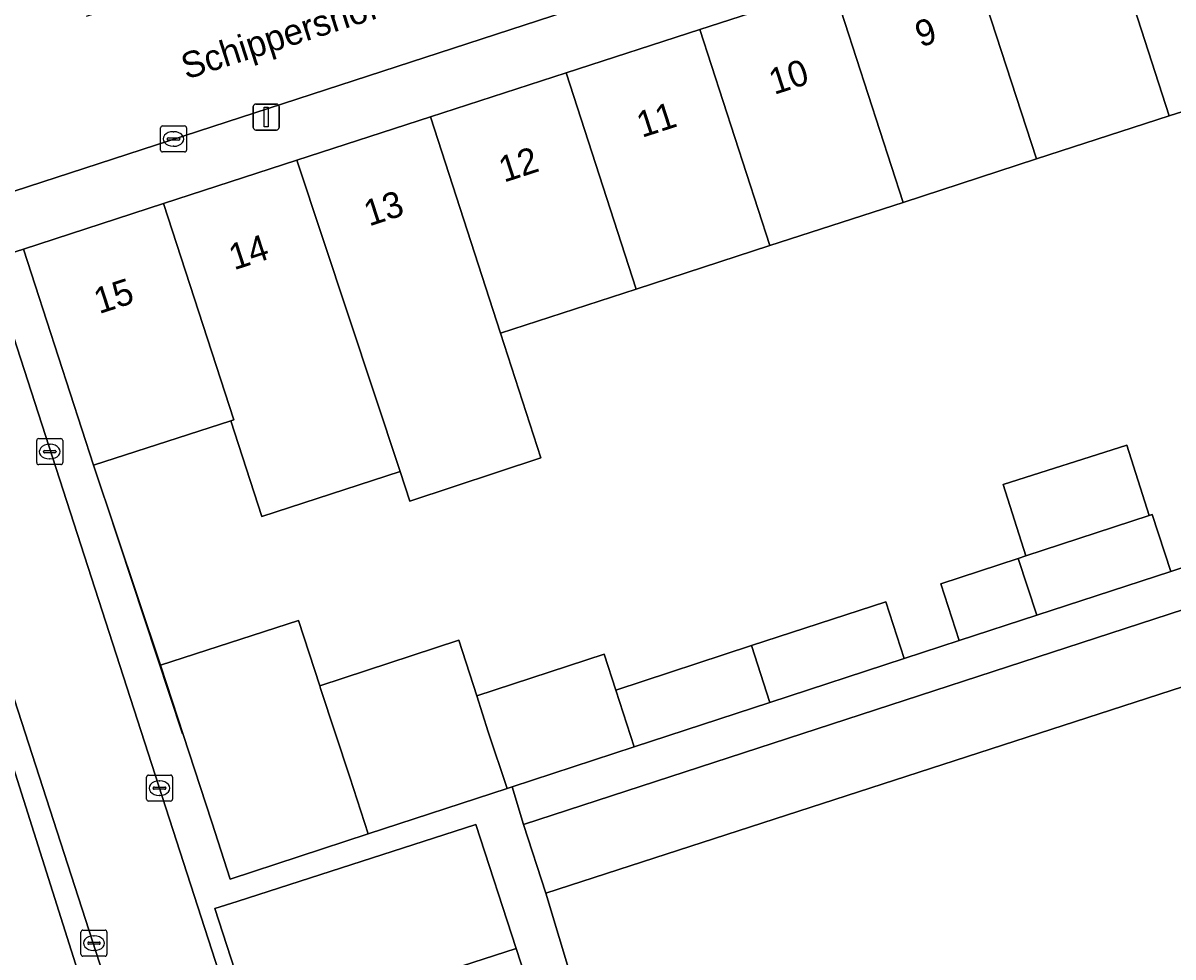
# Model space of a CAD drawing. Extents: x 159371 to 159986, y 382987 to 383597.
# Drawn here: x 159528.13 to 159572.4, y 383065.02 to 383100.96 of the extents above; entities that cross this region are included whole.
import ezdxf

# ---------------------------------------------------------------- set-up
doc = ezdxf.new("R2010")
doc.units = 0
for name, color, linetype in [('IMGEO_Erf', 7, 'Continuous'), ('IMGEO_Kolk', 7, 'Continuous'), ('IMGEO_Lichtmast', 7, 'Continuous'), ('IMGEO_Muur', 7, 'Continuous'), ('IMGEO_Openbare_ruimte_label', 7, 'Continuous'), ('IMGEO_Pand', 7, 'Continuous'), ('IMGEO_Pand_nummerreeks', 7, 'Continuous'), ('IMGEO_Parkeervlak_open', 7, 'Continuous'), ('IMGEO_Rijbaan_lokaal_open', 7, 'Continuous'), ('IMGEO_Voetpad_open', 7, 'Continuous')]:
    doc.layers.add(name, color=color, linetype=linetype)

msp = doc.modelspace()

# ---------------------------------------------------------------- linework, layer by layer
at = {"layer": 'IMGEO_Erf'}
for points in [[(159531.273, 383061.22), (159527.278, 383073.835), (159525.093, 383073.114), (159524.149, 383075.977), (159523.205, 383078.84), (159525.389, 383079.56), (159521.915, 383090.295), (159521.329, 383092.107), (159519.144, 383091.386), (159518.2, 383094.249), (159517.256, 383097.112), (159519.44, 383097.832), (159515.44, 383110.383)], [(159572.778, 383097.554), (159572.256, 383097.384), (159567.152, 383095.728), (159562.01, 383094.058), (159556.888, 383092.396), (159551.737, 383090.724), (159546.51, 383089.027), (159548.062, 383084.231), (159543.03, 383082.562), (159542.654, 383083.696), (159537.327, 383081.967), (159536.129, 383085.657), (159530.85, 383083.943), (159533.432, 383076.248), (159538.735, 383077.972), (159539.558, 383075.456), (159544.911, 383077.206), (159545.601, 383075.064), (159550.509, 383076.67), (159550.955, 383075.289), (159556.179, 383076.998), (159561.346, 383078.689), (159562.057, 383076.502), (159564.173, 383077.194), (159563.462, 383079.381), (159566.447, 383080.358), (159566.732, 383080.451), (159565.861, 383083.206), (159570.629, 383084.713), (159571.485, 383082.006), (159571.606, 383082.046), (159572.318, 383079.858), (159574.54, 383080.585)]]:
    msp.add_lwpolyline(points, dxfattribs=at)
msp.add_lwpolyline([(159590.076, 383081.989), (159589.756, 383082.472), (159584.535, 383080.817), (159583.508, 383080.491), (159581.119, 383079.733), (159581.591, 383078.278), (159548.258, 383067.467), (159552.839, 383052.245), (159554.73, 383049.152), (159594.612, 383075.126)], close=True, dxfattribs=at)
at = {"layer": 'IMGEO_Kolk'}
for p, q in [((159533.428, 383096.072), (159533.428, 383096.924)), ((159533.503, 383096.998), (159534.355, 383096.998)), ((159533.916, 383096.778), (159533.941, 383096.778)), ((159534.429, 383096.924), (159534.429, 383096.072)), ((159533.687, 383096.492), (159533.687, 383096.504)), ((159534.125, 383096.455), (159533.727, 383096.455)), ((159533.73, 383096.541), (159534.128, 383096.541)), ((159534.171, 383096.504), (159534.171, 383096.492)), ((159534.355, 383095.998), (159533.503, 383095.998)), ((159533.939, 383096.218), (159533.914, 383096.218)), ((159528.662, 383084.041), (159528.662, 383084.893)), ((159528.737, 383084.967), (159529.589, 383084.967)), ((159529.15, 383084.747), (159529.175, 383084.747)), ((159529.663, 383084.893), (159529.663, 383084.041)), ((159528.921, 383084.461), (159528.921, 383084.473)), ((159529.359, 383084.424), (159528.961, 383084.424)), ((159528.964, 383084.51), (159529.362, 383084.51)), ((159529.405, 383084.473), (159529.405, 383084.461)), ((159529.589, 383083.967), (159528.737, 383083.967)), ((159529.173, 383084.187), (159529.148, 383084.187)), ((159532.888, 383071.089), (159532.888, 383071.941)), ((159532.963, 383072.015), (159533.815, 383072.015)), ((159533.889, 383071.941), (159533.889, 383071.089)), ((159533.147, 383071.509), (159533.147, 383071.521)), ((159533.585, 383071.472), (159533.187, 383071.472)), ((159533.19, 383071.558), (159533.588, 383071.558)), ((159533.376, 383071.795), (159533.401, 383071.795)), ((159533.631, 383071.521), (159533.631, 383071.509)), ((159533.815, 383071.015), (159532.963, 383071.015)), ((159533.399, 383071.235), (159533.374, 383071.235)), ((159530.365, 383065.122), (159530.365, 383065.974)), ((159530.44, 383066.048), (159531.292, 383066.048)), ((159530.853, 383065.828), (159530.878, 383065.828)), ((159531.366, 383065.974), (159531.366, 383065.122)), ((159530.624, 383065.542), (159530.624, 383065.554)), ((159531.062, 383065.505), (159530.664, 383065.505)), ((159530.667, 383065.591), (159531.065, 383065.591)), ((159530.876, 383065.268), (159530.851, 383065.268)), ((159531.108, 383065.554), (159531.108, 383065.542)), ((159531.292, 383065.048), (159530.44, 383065.048))]:
    msp.add_line(p, q, dxfattribs=at)
for points in [[(159533.428, 383096.072), (159533.428, 383096.924)], [(159533.503, 383096.998), (159534.355, 383096.998)], [(159534.429, 383096.924), (159534.429, 383096.072)], [(159534.355, 383095.998), (159533.503, 383095.998)], [(159528.662, 383084.041), (159528.662, 383084.893)], [(159528.737, 383084.967), (159529.589, 383084.967)], [(159529.663, 383084.893), (159529.663, 383084.041)], [(159529.589, 383083.967), (159528.737, 383083.967)], [(159532.888, 383071.089), (159532.888, 383071.941)], [(159532.963, 383072.015), (159533.815, 383072.015)], [(159533.889, 383071.941), (159533.889, 383071.089)], [(159533.815, 383071.015), (159532.963, 383071.015)], [(159530.365, 383065.122), (159530.365, 383065.974)], [(159530.44, 383066.048), (159531.292, 383066.048)], [(159531.366, 383065.974), (159531.366, 383065.122)], [(159531.292, 383065.048), (159530.44, 383065.048)]]:
    msp.add_lwpolyline(points, dxfattribs=at)
for centre, radius, start, end in [((159533.505, 383096.922), 0.0765, 91.552, 178.448), ((159533.505, 383096.922), 0.0765, 91.552, 178.448), ((159534.353, 383096.922), 0.0765, 1.552, 88.448), ((159534.353, 383096.922), 0.0765, 1.552, 88.448), ((159533.727, 383096.501), 0.0403, 85.8775, 175.7526), ((159533.724, 383096.491), 0.0366, 178.938, 274.7102), ((159534.128, 383096.498), 0.043, 264.8664, 352.4533), ((159534.132, 383096.503), 0.0386, 1.7309, 96.639), ((159533.505, 383096.074), 0.0765, 181.552, 268.448), ((159533.505, 383096.074), 0.0765, 181.552, 268.448), ((159534.353, 383096.074), 0.0765, 271.552, 358.448), ((159534.353, 383096.074), 0.0765, 271.552, 358.448), ((159528.739, 383084.891), 0.0765, 91.552, 178.448), ((159528.739, 383084.891), 0.0765, 91.552, 178.448), ((159529.587, 383084.891), 0.0765, 1.552, 88.448), ((159529.587, 383084.891), 0.0765, 1.552, 88.448), ((159528.961, 383084.47), 0.0403, 85.8775, 175.7526), ((159528.958, 383084.46), 0.0366, 178.938, 274.7102), ((159529.362, 383084.467), 0.043, 264.8664, 352.4533), ((159529.366, 383084.472), 0.0386, 1.7309, 96.639), ((159528.739, 383084.043), 0.0765, 181.552, 268.448), ((159528.739, 383084.043), 0.0765, 181.552, 268.448), ((159529.587, 383084.043), 0.0765, 271.552, 358.448), ((159529.587, 383084.043), 0.0765, 271.552, 358.448), ((159532.965, 383071.939), 0.0765, 91.552, 178.448), ((159532.965, 383071.939), 0.0765, 91.552, 178.448), ((159533.813, 383071.939), 0.0765, 1.552, 88.448), ((159533.813, 383071.939), 0.0765, 1.552, 88.448), ((159533.187, 383071.518), 0.0403, 85.8775, 175.7526), ((159533.184, 383071.508), 0.0366, 178.938, 274.7102), ((159533.588, 383071.515), 0.043, 264.8664, 352.4533), ((159533.592, 383071.52), 0.0386, 1.7309, 96.639), ((159532.965, 383071.091), 0.0765, 181.552, 268.448), ((159532.965, 383071.091), 0.0765, 181.552, 268.448), ((159533.813, 383071.091), 0.0765, 271.552, 358.448), ((159533.813, 383071.091), 0.0765, 271.552, 358.448), ((159530.442, 383065.972), 0.0765, 91.552, 178.448), ((159530.442, 383065.972), 0.0765, 91.552, 178.448), ((159531.29, 383065.972), 0.0765, 1.552, 88.448), ((159531.29, 383065.972), 0.0765, 1.552, 88.448), ((159530.664, 383065.551), 0.0403, 85.8775, 175.7526), ((159530.661, 383065.541), 0.0366, 178.938, 274.7102), ((159531.065, 383065.548), 0.043, 264.8664, 352.4533), ((159531.069, 383065.553), 0.0386, 1.7309, 96.639), ((159530.442, 383065.124), 0.0765, 181.552, 268.448), ((159530.442, 383065.124), 0.0765, 181.552, 268.448), ((159531.29, 383065.124), 0.0765, 271.552, 358.448), ((159531.29, 383065.124), 0.0765, 271.552, 358.448)]:
    msp.add_arc(centre, radius, start, end, dxfattribs=at)
for centre, major_axis, ratio, start_param, end_param in [((159533.915, 383096.498), (-0.387, 0.002), 0.722429, 4.712389, 7.853982), ((159533.94, 383096.498), (-0.39, 0.002), 0.717154, 1.570796, 4.712389), ((159529.149, 383084.467), (-0.387, 0.002), 0.722429, 4.712389, 7.853982), ((159529.174, 383084.467), (-0.39, 0.002), 0.717154, 1.570796, 4.712389), ((159533.375, 383071.515), (-0.387, 0.002), 0.722429, 4.712389, 7.853982), ((159533.4, 383071.515), (-0.39, 0.002), 0.717154, 1.570796, 4.712389), ((159530.852, 383065.548), (-0.387, 0.002), 0.722429, 4.712389, 7.853982), ((159530.877, 383065.548), (-0.39, 0.002), 0.717154, 1.570796, 4.712389)]:
    msp.add_ellipse(centre, major_axis=major_axis, ratio=ratio, start_param=start_param, end_param=end_param, dxfattribs=at)
at = {"layer": 'IMGEO_Lichtmast'}
for p, q in [((159536.999, 383096.943), (159536.999, 383097.743)), ((159536.999, 383097.743), (159536.999, 383096.943)), ((159537.099, 383097.843), (159537.889, 383097.843)), ((159537.889, 383097.843), (159537.099, 383097.843)), ((159537.989, 383097.743), (159537.989, 383096.943)), ((159537.989, 383096.943), (159537.989, 383097.743)), ((159537.889, 383096.843), (159537.099, 383096.843)), ((159537.099, 383096.843), (159537.889, 383096.843))]:
    msp.add_line(p, q, dxfattribs=at)
msp.add_lwpolyline([(159537.419, 383097.718), (159537.569, 383097.718), (159537.569, 383096.968), (159537.419, 383096.968), (159537.419, 383097.718)], dxfattribs=at)
for centre, start, end in [((159537.099, 383097.743), 90, 180), ((159537.099, 383097.743), 90, 180), ((159537.889, 383097.743), 0, 90), ((159537.889, 383097.743), 360, 90), ((159537.099, 383096.943), 180, 270), ((159537.099, 383096.943), 180, 270), ((159537.889, 383096.943), 270, 0), ((159537.889, 383096.943), 270, 0)]:
    msp.add_arc(centre, 0.1, start, end, dxfattribs=at)
at = {"layer": 'IMGEO_Muur'}
for points in [[(159530.85, 383083.943), (159534.267, 383073.62)], [(159527.278, 383073.835), (159531.273, 383061.22)]]:
    msp.add_lwpolyline(points, dxfattribs=at)
at = {"layer": 'IMGEO_Pand'}
for points in [[(159569.577, 383105.707), (159572.256, 383097.384), (159572.778, 383097.554), (159577.533, 383099.097), (159576.724, 383101.831), (159575.821, 383104.635), (159574.918, 383107.441)], [(159569.577, 383105.707), (159564.446, 383104.041), (159567.152, 383095.728), (159572.256, 383097.384)], [(159559.316, 383102.376), (159562.01, 383094.058), (159567.152, 383095.728), (159564.446, 383104.041)], [(159559.316, 383102.376), (159554.184, 383100.71), (159556.888, 383092.396), (159562.01, 383094.058)], [(159551.737, 383090.724), (159556.888, 383092.396), (159554.184, 383100.71), (159549.045, 383099.042)], [(159543.819, 383097.345), (159546.51, 383089.027), (159551.737, 383090.724), (159549.045, 383099.042)], [(159543.819, 383097.345), (159538.679, 383095.677), (159542.654, 383083.696), (159543.03, 383082.562), (159548.062, 383084.231), (159546.51, 383089.027)], [(159533.546, 383094.01), (159536.246, 383085.695), (159536.129, 383085.657), (159537.327, 383081.967), (159542.654, 383083.696), (159538.679, 383095.677)], [(159533.546, 383094.01), (159528.151, 383092.259), (159530.85, 383083.943), (159536.129, 383085.657), (159536.246, 383085.695)], [(159566.732, 383080.451), (159571.485, 383082.006), (159570.629, 383084.713), (159565.861, 383083.206)], [(159571.606, 383082.046), (159571.485, 383082.006), (159566.732, 383080.451), (159566.447, 383080.358), (159567.156, 383078.17), (159572.318, 383079.858)], [(159547.401, 383070.111), (159548.258, 383067.467), (159581.591, 383078.278), (159581.119, 383079.733), (159580.718, 383080.97)], [(159566.447, 383080.358), (159563.462, 383079.381), (159564.173, 383077.194), (159567.156, 383078.17)], [(159561.346, 383078.689), (159556.179, 383076.998), (159556.887, 383074.811), (159562.057, 383076.502)], [(159540.709, 383071.936), (159539.588, 383075.354), (159539.558, 383075.456), (159538.735, 383077.972), (159533.432, 383076.248), (159535.399, 383070.199), (159536.109, 383068.015), (159541.423, 383069.753)], [(159546.046, 383073.683), (159545.601, 383075.064), (159544.911, 383077.206), (159539.558, 383075.456), (159539.588, 383075.354), (159540.709, 383071.936), (159541.423, 383069.753), (159546.776, 383071.503)], [(159556.887, 383074.811), (159556.179, 383076.998), (159550.955, 383075.289), (159551.662, 383073.102)], [(159550.955, 383075.289), (159550.509, 383076.67), (159545.601, 383075.064), (159546.046, 383073.683), (159546.776, 383071.503), (159546.958, 383071.563), (159551.662, 383073.102)]]:
    msp.add_lwpolyline(points, close=True, dxfattribs=at)
at = {"layer": 'IMGEO_Parkeervlak_open'}
msp.add_lwpolyline([(159537.072, 383062.097), (159547.119, 383065.338), (159545.563, 383070.117), (159536.383, 383067.146), (159535.513, 383066.876)], close=True, dxfattribs=at)
at = {"layer": 'IMGEO_Rijbaan_lokaal_open'}
msp.add_lwpolyline([(159523.837, 383120.403), (159543.244, 383126.59), (159541.49, 383132.018), (159516.455, 383123.963), (159516.506, 383123.807), (159512.682, 383122.594), (159512.597, 383122.856), (159512.311, 383122.762), (159522.735, 383090.553), (159526.812, 383091.837), (159526.127, 383093.955), (159550.697, 383101.96), (159549.018, 383107.169), (159530.567, 383101.218)], dxfattribs=at)
msp.add_lwpolyline([(159522.735, 383090.553), (159533.947, 383055.907), (159548.642, 383060.661), (159547.119, 383065.338), (159537.072, 383062.097), (159536.492, 383061.91), (159526.812, 383091.837)], close=True, dxfattribs=at)
at = {"layer": 'IMGEO_Voetpad_open'}
for points in [[(159578.967, 383111.171), (159553.35, 383102.825), (159550.697, 383101.96), (159526.127, 383093.955), (159526.812, 383091.837), (159528.151, 383092.259), (159533.546, 383094.01), (159538.679, 383095.677), (159543.819, 383097.345), (159549.045, 383099.042), (159554.184, 383100.71), (159559.316, 383102.376), (159564.446, 383104.041), (159569.577, 383105.707), (159574.918, 383107.441), (159580.39, 383109.217), (159581.3, 383106.414), (159582.21, 383103.611), (159583.382, 383103.973), (159581.43, 383110.08)], [(159552.839, 383052.245), (159548.258, 383067.467), (159547.401, 383070.111), (159546.958, 383071.563), (159546.776, 383071.503), (159541.423, 383069.753), (159536.109, 383068.015), (159535.399, 383070.199), (159533.432, 383076.248), (159530.85, 383083.943), (159528.151, 383092.259), (159526.812, 383091.837), (159536.492, 383061.91)], [(159533.947, 383055.907), (159522.735, 383090.553), (159521.915, 383090.295), (159525.389, 383079.56), (159526.334, 383076.698), (159527.278, 383073.835), (159531.273, 383061.22)], [(159537.072, 383062.097), (159535.513, 383066.876), (159536.383, 383067.146), (159545.563, 383070.117), (159547.119, 383065.338), (159548.642, 383060.661)]]:
    msp.add_lwpolyline(points, dxfattribs=at)
msp.add_lwpolyline([(159580.718, 383080.97), (159580.361, 383082.489), (159577.366, 383081.509), (159574.54, 383080.585), (159572.318, 383079.858), (159567.156, 383078.17), (159564.173, 383077.194), (159562.057, 383076.502), (159556.887, 383074.811), (159551.662, 383073.102), (159546.958, 383071.563), (159547.401, 383070.111)], close=True, dxfattribs=at)

# ---------------------------------------------------------------- texts
at = {"layer": 'IMGEO_Openbare_ruimte_label'}
msp.add_text('Schippershof', height=1, rotation=17.7643, dxfattribs=at).set_placement((159534.42, 383098.782))
at = {"layer": 'IMGEO_Pand_nummerreeks'}
for s, rotation, p in [('9', 17.985, (159562.678, 383100.018)), ('10', 17.985, (159557.047, 383098.191)), ('11', 17.985, (159551.957, 383096.538)), ('12', 17.985, (159546.649, 383094.815)), ('13', 17.9851, (159541.455, 383093.129)), ('14', 17.985, (159536.259, 383091.442)), ('15', 17.985, (159531.063, 383089.755))]:
    msp.add_text(s, height=1, rotation=rotation, dxfattribs=at).set_placement(p)

doc.saveas('drawing.dxf')
